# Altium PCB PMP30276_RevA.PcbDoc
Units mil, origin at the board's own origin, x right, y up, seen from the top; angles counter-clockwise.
Board outline 4075 x 1575 mil, 2 copper layers (Top Layer, Bottom Layer), stack 62 mil thick; 57 components, 35 nets, 126 pads, 6 vias.
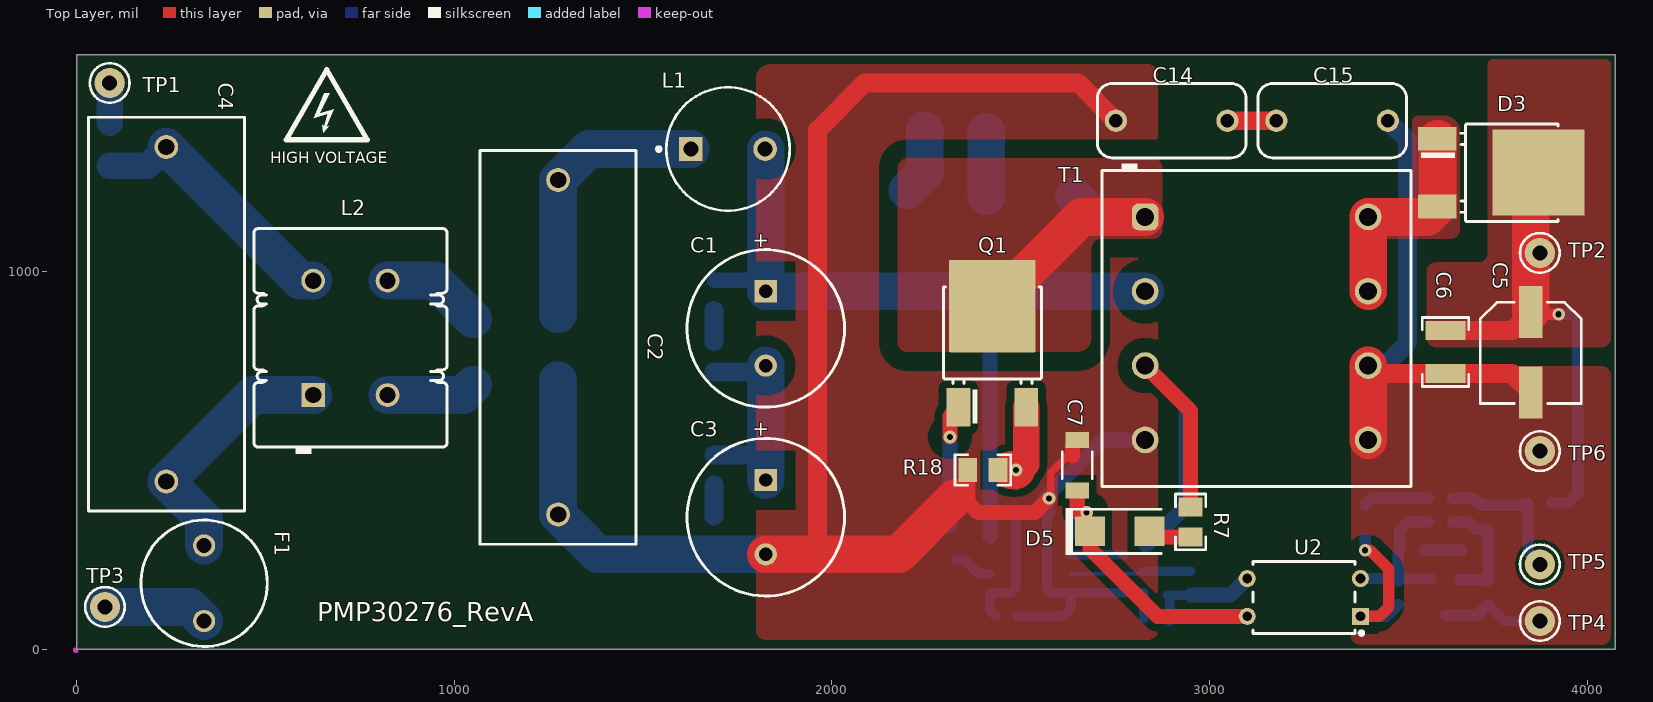
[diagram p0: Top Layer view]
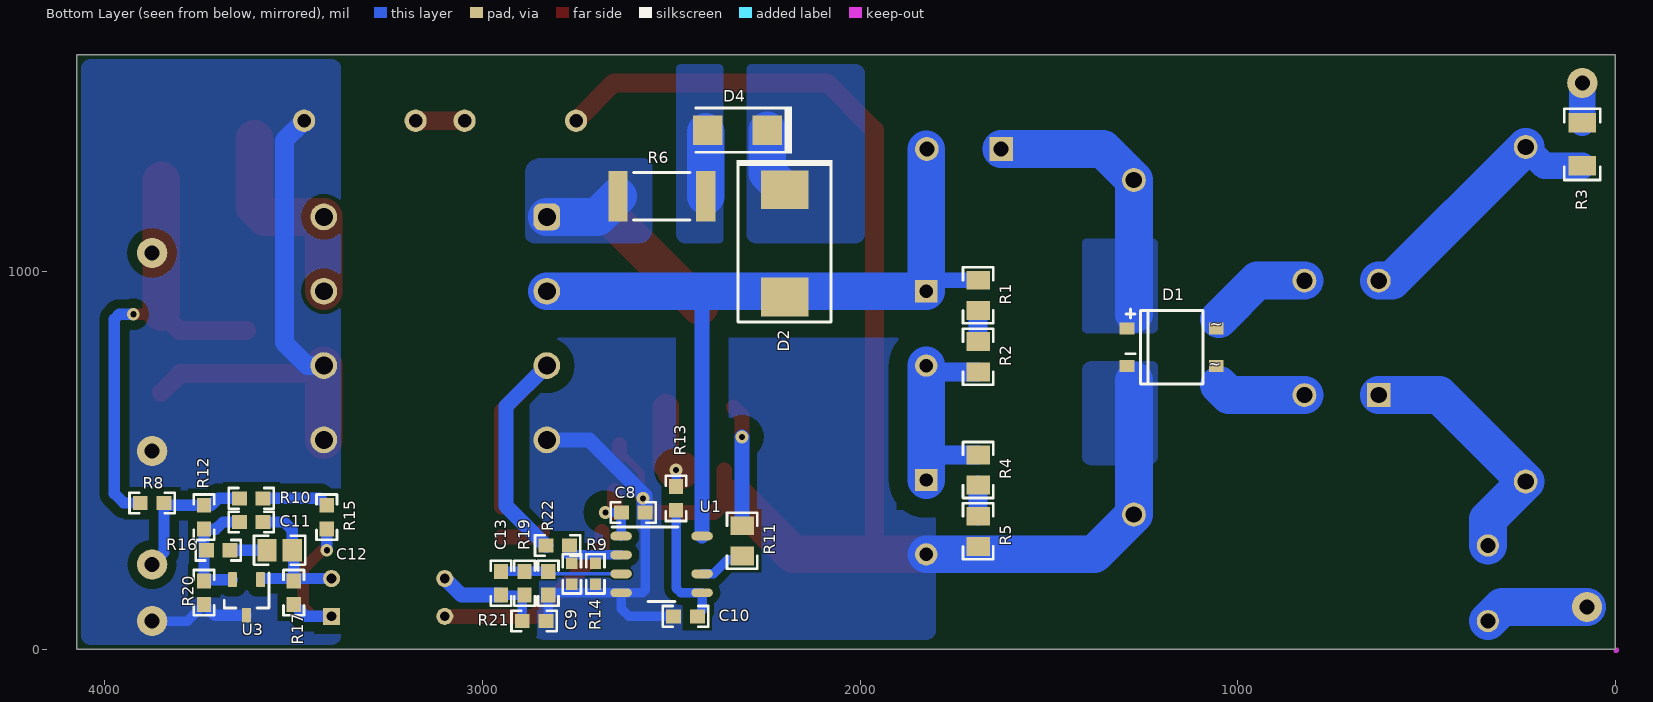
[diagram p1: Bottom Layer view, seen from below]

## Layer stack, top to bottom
Top Solder: solder mask 0.4, Solder Resist, Dk 3.5
Top Layer: signal copper 1.4
Dielectric1: core 59.2, FR-4, Dk 4.8
Bottom Layer: signal copper 1.4
Bottom Solder: solder mask 0.4, Solder Resist, Dk 3.5

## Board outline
0,0 4075,0 4075,1575 0,1575

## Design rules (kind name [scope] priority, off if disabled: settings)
AcuteAngle [All] p1: minimum=4.50000000000000E+0001 checktracksonly=FALSE
AssemblyTestPointUsage [All] p1: valid=2
Clearance Clearance_PGND_NetC1_2 [InNet('PGND') vs InNet('NetC1_2')] p1: gap=50 ignorepadtopadclearanceinfootprint=FALSE
Clearance "Clearance_PGND NETC1_1" [InNet('PGND') vs InNet('NetC1_1')] p2: gap=50 ignorepadtopadclearanceinfootprint=FALSE
Clearance "Clearance_PGND NETC9_1" [InNet('PGND') vs InNet('NetC13_2')] p3: gap=5 ignorepadtopadclearanceinfootprint=FALSE
Clearance Clearance_PGND [InNet('PGND')] p4: gap=20 ignorepadtopadclearanceinfootprint=FALSE except(50: Fill-Fill Fill-Poly Fill-Region Fill-Text Fill-Hole Poly-Poly Poly-Region Poly-Text Poly-Hole Region-Region Region-Text Region-Hole)
Clearance Clearance_Keepouts [((IsTrack Or IsArc) And Not InPoly) And IsFree and IsKeepOut vs ((IsTrack Or IsArc) And Not InPoly) And IsFree and IsKeepOut] p5: gap=0 ignorepadtopadclearanceinfootprint=FALSE
Clearance Clearance_BoardEdge_MountingHoles [OnCopper and InComponentClass('Mounting Holes') vs IsKeepOut] p6: gap=40 ignorepadtopadclearanceinfootprint=FALSE except(0: Arc-Hole Track-Hole SMDPad-Hole THPad-Hole Via-Hole Fill-Hole Poly-Hole Region-Hole Text-Hole)
Clearance Clearance_BoardEdge_Poly [OnCopper and InPoly vs IsKeepOut] p7: gap=25 ignorepadtopadclearanceinfootprint=FALSE except(0: Arc-Hole Track-Hole SMDPad-Hole THPad-Hole Via-Hole Fill-Hole Poly-Hole Region-Hole Text-Hole)
Clearance Clearance_BoardEdge [OnCopper and Not InComponentClass('Logo') and not InComponentClass('FiducialMark') and not InRegion(1000,500,4000,800) and Not IsKeepout vs IsKeepOut] p8: gap=75 ignorepadtopadclearanceinfootprint=FALSE except(0: Arc-Hole Track-Hole SMDPad-Hole THPad-Hole Via-Hole Fill-Hole Poly-Hole Region-Hole Text-Hole)
Clearance Clearance_Poly [InPolygon] p9: gap=25 ignorepadtopadclearanceinfootprint=FALSE except(0: Arc-Hole Track-Hole SMDPad-Hole THPad-Hole Via-Hole Fill-Hole Poly-Hole Region-Hole Text-Hole)
Clearance [All] p10: gap=7.87 ignorepadtopadclearanceinfootprint=FALSE except(0: Arc-Hole Track-Hole SMDPad-Hole THPad-Hole Via-Hole Fill-Hole Poly-Hole Region-Hole Text-Hole)
ComponentClearance ComponentClearance_MountingHoles_FiducialMarks [InComponentClass('Mounting Holes') vs InComponentClass('FiducialMark')] p1: gap=50 collisioncheckmode=3 verticalgap=10 showdistances=FALSE
ComponentClearance ComponentClearance_Shunt [InComponentClass('Header') vs InComponentClass('Shunt')] p2: gap=0 collisioncheckmode=3 verticalgap=0 showdistances=FALSE
ComponentClearance ComponentClearance_Logo [InComponentClass('Logo')] p3: gap=50 collisioncheckmode=3 verticalgap=10 showdistances=FALSE
ComponentClearance ComponentClearance_ScrewToNut [(HasFootprint('NY PMS 440 0025 PH')) vs (HasFootprint('Keystone_1902C'))] p4: gap=5 collisioncheckmode=3 verticalgap=10 showdistances=FALSE
ComponentClearance ComponentClearance_MountingHoles [InComponentClass('Mounting Holes')] p5: gap=250 collisioncheckmode=3 verticalgap=100000 showdistances=FALSE
ComponentClearance ComponentClearance_SmallPassives [HasFootprint('0201*') or HasFootprint('0402*') or HasFootprint('0508') or HasFootprint('0603*') or HasFootprint('0612') or HasFootprint('0805*') or HasFootprint('0815*') or HasFootprint('0830*') or HasFootprint('1206*') or HasFootprint('1210*') or HasFootprint('1808*') or HasFootprint('1812*') or HasFootprint('1825*') or HasFootprint('2010*') or HasFootprint('2220*') or HasFootprint('2225*') or HasFootprint('2512*') or HasFootprint('2728*') or HasFootprint('3518*') vs HasFootprint('0201*') or HasFootprint('0402*') or HasFootprint('0508') or HasFootprint('0603*') or HasFootprint('0612') or HasFootprint('0805*') or HasFootprint('0815*') or HasFootprint('0830*') or HasFootprint('1206*') or HasFootprint('1210*') or HasFootprint('1808*') or HasFootprint('1812*') or HasFootprint('1825*') or HasFootprint('2010*') or HasFootprint('2220*') or HasFootprint('2225*') or HasFootprint('2512*') or HasFootprint('2728*') or HasFootprint('3518*')] p6: gap=20 collisioncheckmode=3 verticalgap=10 showdistances=FALSE
ComponentClearance ComponentClearance_THtoSMT [IsThruComponent vs IsSMTComponent] p7: gap=20 collisioncheckmode=3 verticalgap=30 showdistances=FALSE
ComponentClearance ComponentClearance_THtoTH [IsThruComponent vs IsThruComponent] p8: gap=20 collisioncheckmode=3 verticalgap=30 showdistances=FALSE
ComponentClearance [All] p9: gap=20 collisioncheckmode=3 verticalgap=10 showdistances=FALSE
DiffPairsRouting [All] p1: maxlimit=100 minlimit=10 mostfreqgap=10 toplayer_minwidth=15 toplayer_maxwidth=15 toplayer_prefwidth=15 bottomlayer_minwidth=15 bottomlayer_maxwidth=15 bottomlayer_prefwidth=15 maxuncoupledlength=1000
FabricationTestPointUsage TestPointUsage [All] p1: valid=2 allowmultiple=FALSE
FabricationTestpoint Testpoint [All] p1: side=3 testpointundercomponent=TRUE minsize=40 maxsize=100 preferedsize=60 minholesize=0 maxholesize=40 preferedholesize=32 testpointgrid=1 allowsidetop=TRUE allowsidebottom=TRUE usegrid=TRUE gridtolerance=0.01
FanoutControl Fanout_LCC [IsLCC] p1: bgadir=Out bgaviamode=Centered fanoutstyle=Auto fanoutdirection=Alternating viagrid=1 // Fanout_LCC (Default Rule)
FanoutControl Fanout_BGA [IsBGA] p2: bgadir=Out bgaviamode=Centered fanoutstyle=Auto fanoutdirection=Alternating viagrid=1 // Fanout_BGA (Default Rule)
FanoutControl Fanout_Default [All] p4: bgadir=Out bgaviamode=Centered fanoutstyle=Auto fanoutdirection=Alternating viagrid=1 // Fanout_Default (Default Rule)
FanoutControl Fanout_Small [(CompPinCount < 5)] p5: bgadir=Out bgaviamode=Centered fanoutstyle=Auto fanoutdirection=OutThenIn viagrid=1 // Fanout_Small (Default Rule)
HoleSize [All] p1: absolutevalues=TRUE maxlimit=251 minlimit=8 maxpercent=80.000 minpercent=20.000
MinimumAnnularRing MinimumAnnularRing_ThermalPadVias [IsVia and InAnyComponent] p1: minimumring=5.91
MinimumAnnularRing [All] p2: minimumring=9
MinimumSolderMaskSliver MinimumSolderMaskSliver_Logo [InComponentClass('Logo') vs InComponentClass('Logo')] p1: minsoldermaskwidth=0.7
MinimumSolderMaskSliver [All] p2: minsoldermaskwidth=3.94
PlaneConnect [All] p1: planeconnectstyle=Direct reliefexpansion=10 reliefentries=4 reliefconductorwidth=10 reliefairgap=10
PolygonConnect [All] p1: connectstyle=Direct reliefconductorwidth=10 reliefentries=4 polygonreliefangle="90 Angle" airgapwidth=10
RoutingVias ThermalPadVias [IsVia and InAnyComponent] p1: holewidth=7.87 width=19.68 viastyle="Through Hole" minholewidth=7.87 minwidth=19.68 maxholewidth=12.99 maxwidth=23.62
RoutingVias [All] p2: holewidth=16 width=34 viastyle="Through Hole" minholewidth=7.87 minwidth=26 maxholewidth=40 maxwidth=65
SilkToBoardRegionClearance [Not ((IsComment or IsDesignator) And (Hide <> 'False')) and not InRegion(1000,500,4000,800)] p1:
SilkToSilkClearance SilkToSilkClearance_Pb-FreeLogo [(HasFootprint('Pb-Free_Overlay_Medium') OR HasFootprint('Pb-Free_Overlay_Small')) vs (HasFootprint('Pb-Free_Overlay_Medium') OR HasFootprint('Pb-Free_Overlay_Small'))] p1: silktosilkclearance=0
SilkToSilkClearance [All] p2: silktosilkclearance=4
SilkToSolderMaskClearance SilkToComonentPadClearance [IsPad and InAnycomponent] p1: minsilkscreentomaskgap=5 clearancetoexposedcopper=TRUE
SilkToSolderMaskClearance "Silk to Solder Mask Opening" [All] p2: minsilkscreentomaskgap=4 clearancetoexposedcopper=FALSE
SolderMaskExpansion [All] p1: expansion=1.97
Width [All] p1: maxlimit=100 minlimit=6 preferedwidth=10 checkconnectedcopper=TRUE
15 further rules are at their usual default settings.

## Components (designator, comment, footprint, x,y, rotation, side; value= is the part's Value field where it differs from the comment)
C1 "EEU-EE2V150" CAPPR5-10x20 1825,850 r270 top value=15uF
C2 "R474N322050A1K" B32913_2650x1050x1850 1275,800 r270 top value=0.22uF
C3 "EEU-EE2V150" CAPPR5-10x20 1825,350 r270 top value=15uF
C4 "R474N322050A1K" B32913_2650x1050x1850 237.5,887.5 r270 top value=0.22uF
C5 "16SVPF180M" CAPSMT_62_F61 3850,787.5 r270 top value=180uF
C6 "Used in BOM report" 1210 3625,787.5 r270 top value=DNP
C7 "C3216X7R1H475K160AC" 1206_180 2650,487.5 r90 top value=4.7uF
C8 "06035C104KAT2A" 0603 2600.95,362.5 r180 bottom value=0.1uF
C9 "Used in BOM report" 0603_HV 2763.45,200 r270 bottom value=DNP
C10 "Used in BOM report" 0603 2462.5,87.5 r0 bottom value=DNP
C11 "C0603C103J5RACTU" 0603 3612.5,337.5 r180 bottom value=0.01uF
C12 "Used in BOM report" 0805 3537.5,262.5 r0 bottom value=DNP
C13 "C1608X7R1H473K080AA" 0603 2950.95,175 r90 bottom value=0.047uF
C14 "DE2E3KY472MB3BM02F" KY_1000x500x1300 2900,1400 r180 top value=4700pF
C15 "DE2E3KY472MB3BM02F" KY_1000x500x1300 3325,1400 r180 top value=4700pF
D1 "MB8S-TP" MBS-1 1175,800 r180 bottom value=800V
D2 "SMCJ180A-TP" SMC_265 2200,1075 r270 bottom value=180V
D3 "MBRD5150TR" DPAK 3737.5,1262.5 r0 top
D4 "US1K-13-F" SMA 2325,1375 r0 bottom value=800V
D5 "ES1D-13-F" SMA 2762.5,312.5 r0 top value=200V
F1 "37205000001" FUSE_372 337.5,175 r270 top
"HIGH VOLTAGE" "DANGER HIGH VOLTAGE" IEC_HighVoltage_Small 662.5,1437.5 r0 top
L1 "768772221" WE-TI_8095 1725,1325 r0 top value=220uH
L2 "744822110" WE-CMB_Type_S 725,825 r90 top value=DNP
Q1 "IPD80R4K5P7ATMA1" DPAK 2425,775 r90 top value=800V
R1 "CRCW08051M50JNEA" 0805_HV 1687.5,937.5 r90 bottom value=1.5Meg
R2 "CRCW08051M50JNEA" 0805_HV 1687.5,775 r90 bottom value=1.5Meg
R3 "CRCW12060000Z0EA" 1206 87.5,1337.5 r270 bottom value=0
R4 "CRCW08051M50JNEA" 0805_HV 1687.5,475 r90 bottom value=1.5Meg
R5 "CRCW08051M50JNEA" 0805_HV 1687.5,312.5 r90 bottom value=1.5Meg
R6 "CRCW25120000Z0EG" 2512 2525,1200 r180 bottom value=0
R7 "CRCW080533R0JNEA" 0805_HV 2950,337.5 r90 top value=33
R8 "CRCW060349R9FKEA" 0603 3875,387.5 r0 bottom value=49.9
R9 "CRCW0603127KFKEA" 0603 2800.95,275 r0 bottom value=127k
R10 "CRCW06030000Z0EA" 0603 3612.5,400 r0 bottom value=0
R11 "CRCW08050000Z0EA" 0805_HV 2312.5,287.5 r90 bottom value=0
R12 "CRCW0603100KFKEA" 0603 3737.5,350 r90 bottom value=100k
R13 "CRCW06031K69FKEA" 0603 2487.5,400 r90 bottom value=1.69k
R14 "CRCW060334K8FKEA" 0603_HV 2700.95,200 r90 bottom value=34.8k
R15 "CRCW06032K00FKEA" 0603 3412.5,350 r90 bottom value=2.00k
R16 "Used in BOM report" 0603 3700,262.5 r180 bottom value=DNP
R17 "Used in BOM report" 0603 3500,150 r270 bottom value=DNP
R18 "ERJ-6RQF1R5V" 0805_HV 2400,475 r0 top value=1.50
R19 "CRCW0603100KFKEA" 0603 2888.45,175 r270 bottom value=100k
R20 "CRCW060326K1FKEA" 0603 3737.5,150 r90 bottom value=26.1k
R21 "CRCW060310K0FKEA" 0603 2863.45,75 r0 bottom value=10.0k
R22 "CRCW060322K1FKEA" 0603 2825.95,175 r90 bottom value=22.1k
T1 "750370833" Wurth_750370833 3125,850 r0 top value=1.5mH
TP1 "5000" Keystone5000 87.5,1500 r0 top
TP2 "5000" Keystone5000 3875,1050 r90 top
TP3 "5000" Keystone5000 75,112.5 r0 top
TP4 "5001" Keystone5001 3875,75 r0 top
TP5 "5000" Keystone5000 3875,225 r90 top
TP6 "5001" Keystone5001 3875,525 r90 top
U1 "UCC28740DR" D0007A_N 2525.95,225 r180 bottom
U2 "FOD817A" DIP-4 3250,137.5 r180 top
U3 "ATL431AIDBZR" DBZ0003A_N 3625,137.5 r270 bottom

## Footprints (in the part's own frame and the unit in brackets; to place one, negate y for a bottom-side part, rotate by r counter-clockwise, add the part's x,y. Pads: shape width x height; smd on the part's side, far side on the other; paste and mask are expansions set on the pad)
0603 [mm] "0603 from SM-752 data"
  rect 1x0.95 smd: 1(-0.8,0) 2(0.8,0)
  silkscreen extent -1.52,-0.69 1.52,0.69, body extent -0.87,-0.47 0.87,0.47, height 1
0603_HV [mil] "Ernesto recommended land pattern.  26 mil between pads."
  rect 30x30 smd: 1(-28,0) 2(28,0)
  silkscreen extent -52,-24 52,24, body extent -34,-19 34,19, height 39
0805 [mm] "0805 from SM-752 data"
  rect 1.3x1.5 smd: 1(-0.85,0) 2(0.85,0)
  silkscreen extent -1.72,-0.97 1.72,0.97, body extent -1.1,-0.72 1.1,0.72, height 1.45
0805_HV [mil] "0805 with 30mil clearance between pads"
  rect 50x63 smd: 1(-40,0) 2(40,0)
  silkscreen extent -74,-40 74,40, body extent -43,-29 43,29, height 57
1206 [mm] "1206 from SM-752 data"
  rect 1.3x1.85 smd: 1(-1.45,0) 2(1.45,0)
  silkscreen extent -2.4,-1.21 2.4,1.21, body extent -1.7,-0.9 1.7,0.9, height 1.35
1206_180 [mm] "1206_180"
  rect 1.1x1.6 smd: 1(-1.7,0) 2(1.7,0)
  silkscreen extent -0.9,-1 0.9,1, body extent -1.75,-0.95 1.75,0.95, height 1.8
1210 [mm] "1210 from SM-752 data"
  rect 1.3x2.7 smd: 1(-1.45,0) 2(1.45,0)
  silkscreen extent -2.32,-1.57 2.32,1.57, body extent -1.7,-1.35 1.7,1.35, height 1.35
2512 [mm] "Chip Resistor, Body 6.3x3.2mm, IPC Medium Density"
  rect 1.3x3.4 smd: 1(-2.95,0) 2(2.95,0)
  silkscreen extent -1.9,-1.6 1.9,1.6, body extent -3.22,-1.67 3.22,1.67, height 0.71
B32913_2650x1050x1850 [mm] "TH, 2-Leads, Body 26.5x10.5mm, Pin Spacing 22.5mm"
  round 1.6 hole 1.1: 1(-11.25,0) 2(11.25,0)
  silkscreen extent -13.25,-5.25 13.25,5.25, body extent -13.25,-5.25 13.25,5.25, height 18.5
CAPPR5-10x20 [mm] "Capacitor, Electrolytic, Radial; Body 10 x 20 mm (Dia.xH typ); Pin Spacing 5 mm (typ)"
  rect 1.5x1.5 hole 0.9: 1(-2.5,0)
  round 1.5 hole 0.9: 2(2.5,0)
  silkscreen extent -5.3,-5.3 5.3,5.3, body extent -5.21,-5.24 5.24,5.24, height 22.01
CAPSMT_62_F61 [mm] "6.3 x 5.8mm:  Chemi-Con F61"
  rect 3.5x1.6 smd: 1(-2.675,0.025) 2(2.725,0.025)
  silkscreen extent -3.34,-3.38 3.46,3.42, body extent -3.37,-3.38 3.46,3.43, height 6.1
D0007A_N [mm] "SOIC, 7-Leads, Body 4.9x3.9mm, Pitch 1.27mm, IPC Medium Density"
  oval 1.45x0.6 smd: 1(-2.725,1.905) 2(-2.725,0.635) 3(-2.725,-0.635) 4(-2.725,-1.905) 5(2.725,-1.905) 6(2.725,-0.635) 8(2.725,1.905)
  silkscreen extent -3.32,-2.5 1.1,2.52, body extent -3.01,-2.45 3.01,2.45, height 1.75
DBZ0003A_N [mm] "SOT23, 3-Leads, Body 2.9x1.3mm, Pitch 0.95mm, Lead Span 2.4mm, IPC Medium Density"
  rrect17% 1x0.6 smd: 1(-1.2,0.95) 2(-1.2,-0.95) 3(1.2,0)
  silkscreen extent -1.65,-1.5 0.7,1.5, body extent -1.26,-1.46 1.26,1.46, height 0.98
DIP-4 [mm] "DIP, 4-Leads, Body 6.86x4.83mm, Pitch 2.54mm"
  rect 1.15x1.15 hole 0.65: 1(-3.81,1.27)
  round 1.15 hole 0.65: 2(-3.81,-1.27) 3(3.81,-1.27) 4(3.81,1.27)
  silkscreen extent -4,-2.41 3.43,2.52, body extent -4.02,-2.41 4.02,2.41, height 5.59
DPAK [mm] "D-PAK, 3-Pads, Body 6.22x6.73mm (max), TO-252AA using nominal STEP model"
  rrect6% 2.6x1.6 smd: 1(-3.4,2.28) 3(-3.4,-2.28)
  rrect2% 6.2x5.8 smd paste-2.9: 4(3.4,0)
  silkscreen extent -4.5,-3.3 4.7,3.28, body extent -3.86,-3.29 5.84,3.29, height 2.48
FUSE_372 [mm] "LITTELFUSE"
  round 1.5 hole 1: 1(-2.54,0) 2(2.54,0)
  silkscreen extent -4.25,-4.25 4.25,4.25, body extent -4.25,-4.25 4.25,4.25, height 8
IEC_HighVoltage_Small [mil]
  silkscreen extent -107,-88 107,97
Keystone5000 [mil] "For Keystone 500x miniature loop terminals"
  round 80 hole 40: 1(0,0)
  silkscreen extent -52,-52 52,52, body extent -49,-49 49,49, height 182
Keystone5001 [mil] "For Keystone 500x miniature loop terminals"
  round 80 hole 40: 1(0,0)
  silkscreen extent -52,-52 52,52, body extent -49,-49 49,49, height 182
KY_1000x500x1300 [mm] "MuRata"
  round 1.5 hole 0.9: 1(-3.75,0) 2(3.75,0)
  silkscreen extent -5,-2.5 5,2.5, body extent -5,-2.5 5,2.5, height 13
MBS-1 [mm] "SOP, 4-Leads, Body 4.95x4.2mm"
  rect 1x0.8 smd: 1(-3,1.27) 2(3,1.27) 3(3,-1.27) 4(-3,-1.27)
  silkscreen extent -3.08,-2.48 2.1,2.56, body extent -3.45,-2.47 3.45,2.48, height 2.9
SMA [mm] "Molded Diode, 2-Leads, Body 4.3x2.6mm, IPC Medium Density, based on OnSemi component dimensions and land pattern"
  rect 2x2 smd: 1(-2,0) 2(2,0)
  silkscreen extent -3.66,-1.57 2.79,1.57, body extent -2.6,-1.3 2.6,1.3, height 2.42
SMC_265 [mm] "SMD, 2-Leads, Body 7.15x6.25mm"
  rect 2.6x3.2 smd: 1(-3.6,0) 2(3.6,0)
  silkscreen extent -5.6,-3.22 5.3,3.23, body extent -4.08,-3.13 4.08,3.13, height 2.65
WE-CMB_Type_S [mm] "TH, 4-Leads, Body 14.7x13mm"
  rect 1.6x1.6 hole 1.1: 1(-3.85,2.5)
  round 1.6 hole 1.1: 2(-3.85,-2.5) 3(3.85,-2.5) 4(3.85,2.5)
  silkscreen extent -7.8,-6.5 7.35,6.5, body extent -7.77,-6.5 7.77,6.5, height 20
WE-TI_8095 [mm] "Wurth WE-TI 8095"
  rect 1.6x1.6 hole 1: 1(-2.5,0)
  round 1.6 hole 1: 2(2.5,0)
  silkscreen extent -4.79,-4.15 4.15,4.15, body extent -4.12,-4.14 4.15,4.14, height 10
Wurth_750370833 [mm] "TH, 8-Leads, Body 21.24x20.78mm"
  rrect50% 1.8x1.8 hole 1.2: 1(-7.5,7.5)
  round 1.8 hole 1.2: 2(-7.5,2.5) 3(-7.5,-2.5) 4(-7.5,-7.5) 5(7.5,-7.5) 6(7.5,-2.5) 7(7.5,2.5) 8(7.5,7.5)
  silkscreen extent -10.39,-10.62 10.39,11.1, body extent -10.39,-10.62 10.39,10.62, height 15.88

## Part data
C1 C3: library part Capacitor_Polarized, "CAP, [Technology], 15uF, 350V, +/-xx%, xxOhm ESR, [MountType]", Alternate Manufacturer=-, Case/Package=Radial, Dielectric Material=Aluminium, Leakage Current=325uA, Manufacturer="Used in BOM report", Max Operating Temperature=105°C, Min Operating Temperature=-25°C, Package Quantity=200, Ripple Current=480mA, Supplier Part Number 1=P13651-ND, Tolerance_%=20%, Voltage=350V
C2 C4: library part B32913B5224K000, "CAP, Film, 0.22 µF, 440VAC,+/- 10%, TH", Cap_Case=26.5x10.5x18.5mm, Case/Package=Radial, Dielectric=PP, Manufacturer=TDK, Max Operating Temperature=110°C, Min Operating Temperature=-40°C, Tolerance_%=10, Value2=440VAC, ValueDisplayed=0.22µF, Voltage Rating (AC)=440V, Voltage Rating (DC)=1kV
C5: "CAP, Aluminum Polymer, 180 µF, 16 V,+/- 20%, 0.022 ohm, F61 SMD", Manufacturer=Panasonic, Tolerance_%=20, Value1="0.022 ohm", Value2=16V, ValueDisplayed=180µF
C6 C9 C10 C12: library part Capacitor, "CAP, CERM, xxxF, xxV, [TempCo], xx%, [PackageReference]", Alternate Manufacturer=-
C7: "CAP, CERM, 4.7 µF, 50 V,+/- 10%, X7R, 1206", Cap_Case=1206, Manufacturer=TDK, Supplier Part Number 1=445-8032-1-ND, TempCo=X7R, Tolerance_%=10, Value1="0.003158 ohm", Value2=50V, ValueDisplayed=4.7µF
C8: "CAP, CERM, 0.1 µF, 50 V, +/- 10%, X7R, 0603", Cap_Case=0603, Manufacturer=AVX, Supplier Part Number 1=478-5052-1-ND, TempCo=X7R, Tolerance_%=10, Value1=Unknown, Value2=50V, ValueDisplayed=0.1µF
C11: "CAP, CERM, 0.01 µF, 50 V, +/- 5%, X7R, 0603", Cap_Case=0603, Manufacturer=Kemet, Supplier Part Number 1=399-1092-1-ND, TempCo=X7R, Tolerance_%=5, Value1=Unknown, Value2=50V, ValueDisplayed=0.01µF
C13: "CAP, CERM, 0.047 µF, 50 V,+/- 10%, X7R, 0603", Cap_Case=0603, Manufacturer=TDK, Supplier Part Number 1=445-1313-1-ND, TempCo=X7R, Tolerance_%=10, Value1="0.049007 ohm", Value2=50V, ValueDisplayed=0.047µF
C14 C15: "CAP, CERM, 4700 pF, X1 250 VAC/Y2 300 VAC, +/- 20%, E, 10x5x13mm", Cap_Case=10x5x13mm, Manufacturer=MuRata, Supplier Part Number 1=490-9484-ND, TempCo=E, Tolerance_%=20, ValueDisplayed=4700pF
D1: "Diode, Switching-Bridge, 800 V, 0.5 A, TO269AA", Manufacturer="Micro Commercial Components", Supplier Part Number 1=MB8S-TPMSDKR-ND, Value1=0.5A, Value2=1V
D2: library part SMCJ160A-TP, "Diode, TVS, Uni, 180 V,", Manufacturer="Micro Commercial Components", Supplier Part Number 1=SMCJ180A-TPMSCT-ND, Value1=W
D3: library part DIODE_SCHOTTKY_A13C4, "Diode, Schottky, 150V, 5A, [PackageReference]", Alternate Manufacturer=-, Manufacturer="SMC Diode Solutions"
D4: "Diode, Fast Rectifier, 800 V, 1 A, SMA", Manufacturer="Diodes Inc.", Supplier Part Number 1=US1K-FDICT-ND, Value1=1A, Value2=1.7V
D5: "Diode, Ultrafast, 200 V, 1 A, SMA", Manufacturer="Diodes Inc.", Supplier Part Number 1=ES1D-FDICT-ND, Value1=1A, Value2=0.92V
F1: "Fuse, 0.5 A, 250VAC/VDC, TH", Irating_A=0.5, Manufacturer=Littelfuse, Supplier Part Number 1=WK4241CT-ND
"HIGH VOLTAGE": library part IEC_HighVoltage, "IEC 61010-1 High Voltage Warning"
L1: library part 768772681, "Inductor, Unshielded Drum Core, Powdered Iron, 220 µH,", Case/Package=Radial, Current Rating=900mA, Manufacturer="Wurth Elektronik", Max Operating Temperature=125°C, Min Operating Temperature=-40°C, Package Quantity=140, Saturation Current=1.3A, Self Resonant Frequency=3.7MHz, Supplier Part Number 1=732-4217-ND, Test Frequency=100KHz, Tolerance_%=10%, Value1="1.68 ohm", Value2=0.76A, ValueDisplayed=220µH
L2: "Coupled inductor, 10 mH, 1 A, 0.36 ohm, TH", Manufacturer="Wurth Elektronik", Supplier Part Number 1=732-1442-ND, ValueDisplayed=10mH
Q1: library part IPD80R1K0CEBTMA1, "MOSFET, N-CH, 800 V, DPAK", Alternate Manufacturer=None, Case/Package=TO-252-3, Continuous Drain Current (ID)=1.5A, Manufacturer="Infineon Technologies", Max Operating Temperature=150°C, Max Power Dissipation=13W, Min Operating Temperature=-55°C, Value1="? ohm"
R1 R2 R4 R5: "RES, 1.5 M, 5%, 0.125 W, 0805", Manufacturer=Vishay-Dale, Power_W=0.125, Supplier Part Number 1=541-1.5MACT-ND, TempCo="200 ppm/C", Tolerance_%=5, Value1=5%, Value2=0.125W, Value_Code=1M50, ValueDisplayed=1.5M
R3: "RES, 0, 5%, 0.25 W, 1206", Manufacturer=Vishay-Dale, Power_W=0.25, Supplier Part Number 1=541-0.0ECT-ND, TempCo="200 ppm/C", Tolerance_%=5, Value1=5%, Value2=0.25W, Value_Code=0000, ValueDisplayed=0
R6: "RES, 0, 5%, 1 W, AEC-Q200 Grade 0, 2512", Manufacturer=Vishay-Dale, Power_W=1, Supplier Part Number 1=541-0.0XCT-ND, TempCo=ppm/C, Tolerance_%=5, Value1=5%, Value2=1W, Value_Code=0000, ValueDisplayed=0
R7: "RES, 33, 5%, 0.125 W, 0805", Manufacturer=Vishay-Dale, Power_W=0.125, Supplier Part Number 1=541-33ACT-ND, TempCo="200 ppm/C", Tolerance_%=5, Value1=5%, Value2=0.125W, Value_Code=33R0, ValueDisplayed=33
R8: "RES, 49.9, 1%, 0.1 W, 0603", Manufacturer=Vishay-Dale, Power_W=0.1, Supplier Part Number 1=541-49.9HCT-ND, TempCo="100 ppm/C", Tolerance_%=1, Value1=1%, Value2=0.1W, Value_Code=49R9, ValueDisplayed=49.9
R9: "RES, 127 k, 1%, 0.1 W, 0603", Manufacturer=Vishay-Dale, Power_W=0.1, Supplier Part Number 1=541-127KHCT-ND, TempCo="100 ppm/C", Tolerance_%=1, Value1=1%, Value2=0.1W, Value_Code=127k
R10: "RES, 0, 5%, 0.1 W, 0603", Manufacturer=Vishay-Dale, Power_W=0.1, Supplier Part Number 1=541-0.0GCT-ND, TempCo="200 ppm/C", Tolerance_%=5, Value1=5%, Value2=0.1W, Value_Code=0000, ValueDisplayed=0
R11: "RES, 0, 5%, 0.125 W, 0805", Manufacturer=Vishay-Dale, Power_W=0.125, Supplier Part Number 1=541-0.0ACT-ND, TempCo="200 ppm/C", Tolerance_%=5, Value1=5%, Value2=0.125W, Value_Code=0000, ValueDisplayed=0
R12 R19: "RES, 100 k, 1%, 0.1 W, 0603", Manufacturer=Vishay-Dale, Power_W=0.1, Supplier Part Number 1=541-100KHCT-ND, TempCo="100 ppm/C", Tolerance_%=1, Value1=1%, Value2=0.1W, Value_Code=100k
R13: "RES, 1.69 k, 1%, 0.1 W, 0603", Manufacturer=Vishay-Dale, Power_W=0.1, Supplier Part Number 1=541-1.69KHCT-ND, TempCo="100 ppm/C", Tolerance_%=1, Value1=1%, Value2=0.1W, Value_Code=1k69, ValueDisplayed=1.69k
R14: "RES, 34.8 k, 1%, 0.1 W, 0603", Manufacturer=Vishay-Dale, Power_W=0.1, Supplier Part Number 1=541-34.8KHCT-ND, TempCo="100 ppm/C", Tolerance_%=1, Value1=1%, Value2=0.1W, Value_Code=34k8, ValueDisplayed=34.8k
R15: "RES, 2.00 k, 1%, 0.1 W, 0603", Manufacturer=Vishay-Dale, Power_W=0.1, Supplier Part Number 1=541-2.00KHCT-ND, TempCo="100 ppm/C", Tolerance_%=1, Value1=1%, Value2=0.1W, Value_Code=2k00, ValueDisplayed=2.00k
R16 R17: library part Resistor, "RES, xxx ohm, x%, xW, [PackageReference]", Alternate Manufacturer=-
R18: "RES, 1.50, 1%, 0.125 W, 0805", Manufacturer=Panasonic, Power_W=0.125, Supplier Part Number 1=P1.5DCT-ND, TempCo="200 ppm/C", Tolerance_%=1, Value1=1%, Value2=0.125W, Value_Code=1R50, ValueDisplayed=1.50
R20: "RES, 26.1 k, 1%, 0.1 W, 0603", Manufacturer=Vishay-Dale, Power_W=0.1, Supplier Part Number 1=541-26.1KHCT-ND, TempCo="100 ppm/C", Tolerance_%=1, Value1=1%, Value2=0.1W, Value_Code=26k1, ValueDisplayed=26.1k
R21: "RES, 10.0 k, 1%, 0.1 W, 0603", Manufacturer=Vishay-Dale, Power_W=0.1, Supplier Part Number 1=541-10.0KHCT-ND, TempCo="100 ppm/C", Tolerance_%=1, Value1=1%, Value2=0.1W, Value_Code=10k0, ValueDisplayed=10.0k
R22: "RES, 22.1 k, 1%, 0.1 W, 0603", Manufacturer=Vishay-Dale, Power_W=0.1, Supplier Part Number 1=541-22.1KHCT-ND, TempCo="100 ppm/C", Tolerance_%=1, Value1=1%, Value2=0.1W, Value_Code=22k1, ValueDisplayed=22.1k
T1: library part CMP-0077094-1, "Transformer, 1500 uH, TH", Manufacturer="Wurth Elektronik", ValueDisplayed=1.5mH
TP1 TP2 TP3 TP5: "Test Point, Miniature, Red, TH", Color=Red, Manufacturer=Keystone, Supplier Part Number 1=36-5000-ND
TP4 TP6: "Test Point, Miniature, Black, TH", Color=Black, Manufacturer=Keystone, Supplier Part Number 1=36-5001-ND
U1: "Constant-Voltage, Constant-Current Flyback Controller Using Opto-Coupler Feedback, D0007A", Alternate Manufacturer="Texas Instruments", Alternate PartNumber=UCC28740D
U2: "Optocoupler, 5 kV, 80-160% CTR, TH", Manufacturer="Fairchild Semiconductor", Supplier Part Number 1=FOD817A-ND, Voltage_Isolation_Vrms=5000V
U3: "2.5V Low Iq Adjustable Precision Shunt Regulator, DBZ0003A (SOT-23-3)", Alternate Manufacturer="Texas Instruments"

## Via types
v1: diameter 34, hole 16, Top Layer to Bottom Layer, 6 vias

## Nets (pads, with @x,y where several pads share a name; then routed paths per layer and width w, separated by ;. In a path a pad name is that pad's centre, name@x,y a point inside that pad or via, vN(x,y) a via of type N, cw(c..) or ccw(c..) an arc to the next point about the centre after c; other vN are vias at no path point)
12Vout: C5.1 C6.1 D3.4 R8.2 TP2.1 | length 1257
  Top Layer w30: C5.1@3869.72,911.58 3893.8,887.5 v1(3925,887.5)
  Top Layer w50: C6.1 3802.73,844.59 C5.1
  Top Layer w100: C5.1 D3.4@3850.97,1242.11
  Bottom Layer w30: R8.2 3950,387.5 3975,412.5 3975,875 3962.5,887.5 v1(3925,887.5)
GND: C5.2 C6.2 C15.1 R20.1 T1.5 T1.6 TP4.1 TP6.1 U3.3 | length 1676
  Top Layer w50: T1.6 3441.44,730.41 C6.2 3800.79,730.41 C5.2
  Top Layer w100: T1.5 T1.6
  Bottom Layer w25: R20.1 3781,75 TP4.1
  Bottom Layer w30: U3.3 3709.25,90.26 R20.1
  Bottom Layer w50: T1.6 3464.07,751.57 3525,812.5 3525,1347.64 C15.1
NetC1_1: C1.1 D2.2 L1.2 R1.2 T1.2 U1.8 | length 2139.1
  Bottom Layer w40: R1.2 C1.1@1795.93,977.5 ; 2412.5,948.43 2418.67,942.26 U1.8
  Bottom Layer w100: L1.2@1825,1323.43 C1.1 2412.5,948.43 T1.2
NetC1_2: C1.2 C3.1 R2.1 R4.2 | length 551.6
  Bottom Layer w50: R4.2 1815,515 ; R2.1 C1.2@1808.43,735
  Bottom Layer w100: C3.1 C1.2
NetC2_1: C2.1 D1.1 L1.1 | length 741
  Bottom Layer w100: 1275,887.5 C2.1 1357.09,1325 L1.1
NetC4_1: C4.1 L2.4 R3.2 | length 706.4
  Bottom Layer w70: R3.2 187.5,1280.41 C4.1
  Bottom Layer w100: C4.1 591.34,976.57 L2.4
NetC4_2: C4.2 F1.1 L2.1 | length 694.9
  Bottom Layer w100: F1.1 337.5,344.59 C4.2 466.34,673.43 L2.1
NetC7_1: C7.1 C8.1 D5.1 U1.1 U2.4 | length 700
  Top Layer w40: 2650,362.5 C7.1 ; D5.1 2683.76,266.24 2862.5,87.5 U2.4
  Bottom Layer w25: U1.1 2633.24,361.71 C8.1 v1(2675,362.5)
NetC9_1: C9.1 R9.1 R14.2 U1.2 | length 141.8
  Bottom Layer w25: U1.2 2775,250
NetC10_1: C10.1 R13.1 U1.5 | length 349.1
  Bottom Layer w25: C10.1@2434.5,87.5 2418.67,103.33 U1.5 2475,150 2487.5,162.5 R13.1
NetC11_1: C11.1 R12.1 R16.1 R20.2 U3.2 | length 310.2
  Bottom Layer w30: C11.1 3687.5,337.5 3706.5,318.5 R12.1 R20.2 ; U3.2 R20.2@3734.25,184.74
NetC11_2: C11.2 C12.1 R17.1 U2.2 U3.1 | length 405.4
  Bottom Layer w25: U3.1@3584.84,187.5 U3.1
  Bottom Layer w30: U2.2 R17.1@3500,187.5 ; R17.1 R17.1@3500,187.5 ; C12.1@3500,258.46 R17.1@3500,187.5 ; C12.1 3504.04,316.54 3525,337.5 C11.2 ; U3.1@3584.84,187.5 R17.1@3500,187.5
NetC12_2: C12.2 R16.2 | length 97.5
  Bottom Layer w30: C12.2 R16.2
NetC13_1: C13.1 R19.2 R21.2 U2.3 | length 291.8
  Bottom Layer w25: R19.2 C13.1 ; R21.2 R19.2@2894.95,137.01
  Bottom Layer w40: C13.1 3056,143.5 U2.3
NetC13_2: C13.2 R19.1 R22.2 U1.3 | length 317.7
  Bottom Layer w10: U1.3 R22.2@2825.95,200
  Bottom Layer w25: R22.2 R19.1 C13.2
NetC14_1: C14.1 C15.2 | length 129.7
  Top Layer w50: C14.1 C15.2
NetD1_2: D1.2 L2.3 | length 268.6
  Bottom Layer w100: L2.3 948.43,976.57 1050,875
NetD1_3: D1.3 L2.2 | length 237.6
  Bottom Layer w100: L2.2 1023.43,673.43 1050,700
NetD2_1: D2.1 D4.1 | length 177.4
  Bottom Layer w100: D2.1 2246.26,1262.99 D4.1
NetD3_1: D3.1 D3.3 T1.7 T1.8 | length 571.1
  Top Layer w100: T1.7 T1.8 3576.18,1145.28 D3.3 D3.1
NetD4_2: D4.2 R6.2 | length 169.9
  Bottom Layer w100: R6.2 D4.2@2408.86,1369.88
NetD5_2: D5.2 R7.1 | length 115
  Top Layer w40: D5.2 2856.24,297.5 R7.1
NetF1_2: F1.2 TP3.1 | length 278
  Bottom Layer w100: TP3.1 300,112.5 F1.2
NetQ1_1: Q1.1 R11.2 | length 323.1
  Top Layer w40: v1(2312.5,562.5) 2312.5,618.41 Q1.1
  Bottom Layer w40: R11.2 v1(2312.5,562.5)
NetQ1_3: Q1.3 R13.2 R18.2 | length 207.4
  Top Layer w70: 2514.76,489.76 Q1.3
  Top Layer w100: v1@2475,475 v1(2487.5,475)
  Bottom Layer w25: R13.2 v1(2487.5,475)
NetQ1_4: Q1.4 R6.1 T1.1 | length 713.9
  Top Layer w100: Q1.4 2661.42,1145.28 T1.1
  Bottom Layer w100: R6.1 2695.87,1145.28 T1.1
NetR1_1: R1.1 R2.2 | length 82.5
  Bottom Layer w50: R2.2 R1.1
NetR3_1: R3.1 TP1.1 | length 105.4
  Bottom Layer w70: R3.1 TP1.1
NetR4_1: R4.1 R5.2 | length 82.5
  Bottom Layer w50: R5.2 R4.1
NetR7_2: R7.2 R9.2 T1.3 | length 988.6
  Top Layer w40: T1.3 2950,631.3 R7.2
  Bottom Layer w40: T1.3 2937.5,643.8 2937.5,380.05 R9.2
NetR8_1: R8.1 R10.2 R12.2 TP5.1 | length 385.2
  Bottom Layer w30: R10.2 3700,400 3718.5,381.5 R12.2 3837.5,381.5 R8.1 3843.5,256.5 TP5.1
NetR10_1: R10.1 R15.2 | length 176.2
  Bottom Layer w30: R15.2 3431,400 R10.1
NetR11_1: R11.1 U1.6 | length 105.7
  Bottom Layer w25: R11.1@2328.45,237.5 2350.95,237.5 2388.45,200 U1.6
NetR15_1: R15.1 R17.2 U2.1 | length 412.4
  Top Layer w30: U2.1 3450,87.5 3475,112.5 3475,212.5 3425,262.5 v1(3412.5,262.5)
  Bottom Layer w30: U2.1 3469,87.5 R17.2 ; v1(3412.5,262.5) 3412.5,293.5
PGND: C2.2 C3.2 C7.2 C8.2 C9.2 C10.2 C14.2 D1.4 R5.1 R14.1 R18.1 R21.1 R22.1 T1.4 U1.4 | length 5098.9
  Top Layer w20: v1(2575,400) 2579.76,404.76 2579.76,467.26 2625,512.5 2637.5,512.5
  Top Layer w40: R18.1 2360,390 2387.5,362.5 2537.5,362.5 v1(2575,400) ; 2637.5,512.5 C7.2@2637.5,541.93
  Top Layer w50: 1962.5,251.57 1962.5,1375 2087.5,1500 2652.36,1500 C14.2
  Top Layer w100: C3.2 1962.5,251.57 2176.57,251.57 2325,400
  Bottom Layer w25: C10.2@2490.5,87.5 2612.5,87.5 2633.24,108.24 U1.4 ; C8.2 2569.46,156.5 2575.95,150 U1.4 ; R21.1@2825.95,81 R22.1 ; R22.1@2825.95,150 U1.4
  Bottom Layer w40: C8.2 v1@2569.46,400 ; v1@2569.46,406.96 2717.22,554.72 T1.4
  Bottom Layer w100: 1275,712.5 C2.2 1380.51,251.57 C3.2

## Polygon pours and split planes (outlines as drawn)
NetQ1_4 on Top Layer "Top Layer-No Net" (solid, remove dead copper, pour order 2): 2200,787.5 cw(c2200,812.5) 2175,812.5 2175,1275 cw(c2200,1275) 2200,1300 2850,1300 cw(c2850,1275) 2875,1275 2875,1112.5 cw(c2850,1112.5) 2850,1087.5 2712.5,1087.5 ccw(c2712.5,1062.5) 2687.5,1062.5 2687.5,825 cw(c2650,825) 2650,787.5
PGND on Top Layer "Top Layer-No Net 1" (solid, pour order 18): 2862.5,50 cw(c2837.5,50) 2837.5,25 1825,25 cw(c1825,50) 1800,50 1800,1512.5 cw(c1837.5,1512.5) 1837.5,1550 2837.5,1550 cw(c2837.5,1525) 2862.5,1525
12Vout on Top Layer "Top Layer-No Net 2" (solid, pour order 20): 4037.5,800 ccw(c4037.5,825) 4062.5,825 4062.5,1550 ccw(c4050,1550) 4050,1562.5 3750,1562.5 ccw(c3750,1550) 3737.5,1550 3737.5,1050 cw(c3712.5,1050) 3712.5,1025 3600,1025 ccw(c3600,1000) 3575,1000 3575,825 ccw(c3600,825) 3600,800
NetD3_1 on Top Layer "Top Layer-No Net 3" (solid, remove dead copper, pour order 22): 3447.5,1087.5 3637.5,1087.5 ccw(c3637.5,1112.5) 3662.5,1112.5 3662.5,1375 ccw(c3625,1375) 3625,1412.5 3550,1412.5 ccw(c3550,1400) 3537.5,1400 3537.5,1212.5 cw(c3512.5,1212.5) 3491.86,1198.4
GND on Top Layer "Top Layer-No Net 4" (solid, remove dead copper, pour order 24): 3375,750 4037.5,750 cw(c4037.5,725) 4062.5,725 4062.5,37.5 cw(c4037.5,37.5) 4037.5,12.5 3400,12.5 cw(c3400,37.5) 3375,37.5
PGND on Bottom Layer "Bottom Layer-No Net" (solid, remove dead copper, pour order 10): 1825,25 cw(c1825,50) 1800,50 1800,800 cw(c1825,800) 1825,825 2837.5,825 cw(c2837.5,787.5) 2875,787.5 2875,62.5 cw(c2837.5,62.5) 2837.5,25
NetD2_1 on Bottom Layer "Bottom Layer-No Net 1" (solid, pour order 12): 2012.5,1075 cw(c2012.5,1100) 1987.5,1100 1987.5,1525 cw(c2012.5,1525) 2012.5,1550 2287.5,1550 cw(c2287.5,1537.5) 2300,1537.5 2300,1100 cw(c2275,1100) 2275,1075
NetD4_2 on Bottom Layer "Bottom Layer-No Net 2" (solid, pour order 14): 2375,1075 cw(c2375,1087.5) 2362.5,1087.5 2362.5,1537.5 cw(c2375,1537.5) 2375,1550 2475,1550 cw(c2475,1537.5) 2487.5,1537.5 2487.5,1100 cw(c2462.5,1100) 2462.5,1075
NetQ1_4 on Bottom Layer "Bottom Layer-No Net 3" (solid, pour order 16): 2575,1300 ccw(c2575,1275) 2550,1275 2550,1112.5 ccw(c2587.5,1112.5) 2587.5,1075 2862.5,1075 ccw(c2862.5,1100) 2887.5,1100 2887.5,1262.5 ccw(c2850,1262.5) 2850,1300
GND on Bottom Layer "Bottom Layer-No Net 4" (solid, remove dead copper, pour order 26): 3375,1537.5 cw(c3400,1537.5) 3400,1562.5 4037.5,1562.5 cw(c4037.5,1537.5) 4062.5,1537.5 4062.5,37.5 cw(c4037.5,37.5) 4037.5,12.5 3400,12.5 cw(c3400,37.5) 3375,37.5
PGND on Bottom Layer "Bottom Layer-No Net 5" (solid, remove dead copper, pour order 28): 1212.5,750 cw(c1225,750) 1225,762.5 1387.5,762.5 cw(c1387.5,737.5) 1412.5,737.5 1412.5,512.5 cw(c1387.5,512.5) 1387.5,487.5 1237.5,487.5 cw(c1237.5,512.5) 1212.5,512.5
NetC2_1 on Bottom Layer "Bottom Layer-No Net 6" (solid, remove dead copper, pour order 30): 1212.5,850 ccw(c1225,850) 1225,837.5 1400,837.5 ccw(c1400,850) 1412.5,850 1412.5,1075 ccw(c1400,1075) 1400,1087.5 1225,1087.5 ccw(c1225,1075) 1212.5,1075

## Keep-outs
Keep-Out Layer:
  lines w10: -5,0 ccw(c0,0) 0,-5 cw(c0,0) -5,0 ; -5,3450 cw(c0,3450) 0,3455 ccw(c0,3450) -5,3450 ; 4950,-5 ccw(c4950,0) 4955,0 cw(c4950,0) 4950,-5 ; 4950,3455 cw(c4950,3450) 4955,3450 ccw(c4950,3450) 4950,3455
  text ".Layer_Name" at 577,-858.49 h60

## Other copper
Top Layer:
  text ".Layer_Name" at 577,-858.49 h60
Bottom Layer:
  text ".Layer_Name" at 577,-858.49 h60

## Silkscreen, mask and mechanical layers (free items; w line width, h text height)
Top Overlay:
  text "PMP30276_RevA" at 637.5,75 h50
  text ".Layer_Name" at 577,-858.49 h40
Bottom Overlay:
  text ".Layer_Name" at 577,-858.49 h30
Top Paste:
  text ".Layer_Name" at 577,-858.49 h60
Bottom Paste:
  text ".Layer_Name" at 577,-858.49 h60
Top Solder:
  text ".Layer_Name" at 577,-858.49 h60
  text ".Layer_Name" at 577,-858.49 h60
Bottom Solder:
  text ".Layer_Name" at 577,-858.49 h60
Drill Guide:
  text ".Layer_Name" at 577,-858.49 h60
M1 Board Outline:
  the board outline again, w10
  text ".Layer_Name" at 577,-858.49 h60
M2 Board Dimensions:
  rectangle: 0,-275 125,-150
  rectangle: 125,-400 500,-275
  lines w7: 0,-275 1000,-275 ; 125,-400 125,-150 ; 250,-400 250,-150 ; 500,-400 500,-150 ; 750,-400 750,-150 ; 0,-400 1000,-400 1000,-150 0,-150 0,-400
  text ".Layer_Name" at 577,-858.49 h60
M3 3D STEP Top:
  text ".Layer_Name" at 577,-858.49 h60
M4 3D STEP Bottom:
  text ".Layer_Name" at 577,-858.49 h60
M5 Assembly Top:
  lines w10: -292,-930.17 6308,-930.17 ; -292,-726.83 6310,-726.83 ; -292,-523.5 -292,-1133.5 3713,-1133.5 6310,-1133.5 6310,-523.5 -291.5,-523.5 -291.5,-1133.5 1284,-1133.5 ; 2173,-1133.5 2173,-523.5 ; 3440,-726.83 3440,-523.5 ; 4280,-726.83 4280,-523.5 ; 4902,-1140 4902,-937.17
  text "PCB VIEWED FROM TOP SIDE" at -228.5,-655.67 h60
  text "BOARD #:" at 2248,-655.67 h60
  text ".PRJ_Number" at 2793.5,-655.67 h60
  text "REV:" at 3638,-655.67 h60
  text ".PCB_Rev" at 3929.5,-655.67 h60
  text "SVN REV:" at 4476,-655.67 h60
  text ".VersionControl_RevNumber" at 4982,-655.67 h60
  text "TID #:" at 2248,-859 h60
  text ".TID" at 2793.5,-859 h60
  text "PLOT NAME =" at -228.5,-1064.34 h60
  text ".plot_File_Name" at 577,-1064.34 h60
  text "GENERATED    :" at 2250,-1064.34 h60
  text ".Print_Date" at 3119.5,-1064.34 h60
  text ".Print_Time" at 3848.5,-1064.34 h60
  text "TEXAS INSTRUMENTS" at 5113,-1064.34 h60
M6 Assembly Bottom:
  lines w10: -292.5,-727.33 6309.5,-727.33 ; -290.5,-930.67 6309.5,-930.67 ; 1115.5,-1140.5 1115.5,-937.67 ; 1737.5,-727.33 1737.5,-524 ; 2577.5,-727.33 2577.5,-524 ; 3844.5,-1134 3844.5,-524 ; 4733.5,-1134 6309,-1134 6309,-524 -292.5,-524 -292.5,-1134 2304.5,-1134 6309.5,-1134 6309.5,-524
  text ".VersionControl_RevNumber" at 1035.5,-656.17 h60
  text "SVN REV:" at 1541.5,-656.17 h60
  text ".PCB_Rev" at 2088,-656.17 h60
  text "REV:" at 2379.5,-656.17 h60
  text ".PRJ_Number" at 3224,-656.17 h60
  text "BOARD #:" at 3769.5,-656.17 h60
  text "PCB VIEWED FROM BOTTOM SIDE" at 6246,-656.17 h60
  text ".TID" at 3224,-859.5 h60
  text "TID #:" at 3769.5,-859.5 h60
  text "TEXAS INSTRUMENTS" at 904.5,-1064.84 h60
  text ".Print_Time" at 2169,-1064.84 h60
  text ".Print_Date" at 2898,-1064.84 h60
  text "GENERATED    :" at 3767.5,-1064.84 h60
  text ".plot_File_Name" at 5440.5,-1064.84 h60
  text "PLOT NAME =" at 6246,-1064.84 h60
M9 Title Sheet:
  drawing of 57 lines, arcs and shapes, not listed
  text "1" at 739.84,8036.5 h70
  text "2" at 3235.5,8036.5 h70
  text "3" at 5724.84,8036.5 h70
  text "4" at 8231.51,8036.5 h70
  text "5" at 10730.5,8036.5 h70
  text "6" at 13235.5,8036.5 h70
  text "A" at -416.5,6893.5 h70
  text "A" at 14383.5,6893.5 h70
  text "B" at -416.5,4513.5 h70
  text "B" at 14383.5,4513.5 h70
  text "C" at -416.5,2138.5 h70
  text "C" at 14383.5,2138.5 h70
  text "PROJECT TITLE:" at 11343.5,277.5 h45
  text ".PRJ_Title" at 11393.5,144.17 h70
  text "DESIGNED FOR:" at 11343.5,-23.5 h45
  text ".PRJ_Customer" at 11393.5,-163.5 h70
  text "D" at -416.5,-231.5 h70
  text "D" at 14383.5,-231.5 h70
  text "FILE NAME:" at 11343.5,-323.5 h45
  text ".PCB_File_Name_No_Path" at 11393.5,-443.5 h70
  text "Texas Instruments (TI) and/or its licensors do not warrant the accuracy or completeness of this specification" at 6374,-605.34 h45
  text "ENGINEER:" at 11343.5,-613.5 h45
  text "LAYOUT BY:" at 12848.5,-613.5 h45
  text "or any information contained therein. TI and/or its licensors do not warrant that this design will meet" at 6329.01,-718 h45
  text ".PRJ_Engineer" at 11393.5,-768.49 h70
  text ".PCB_Layout" at 12899,-768.49 h70
  text "the specifications, will be suitable for your application or fit for any particular purpose, or will operate in" at 6329.01,-830.67 h45
  text ".Layer_Name" at 577,-858.49 h60
  text "ALTIUM DESIGNER VERSION:" at 12848.5,-923.5 h45
  text "an implementation. TI and/or its licensors do not warrant that the design is production worthy. You should" at 6329.01,-943.33 h45
  text "completely validate and test your design implementation to confirm the system functionality for your application." at 6374,-1056 h45
  text ".print_Scale" at 11393.5,-1056.83 h70
  text ".Application_BuildNumber" at 12899,-1056.83 h70
  text "1" at 739.84,-1263.5 h70
  text "2" at 3235.5,-1263.5 h70
  text "3" at 5724.84,-1263.5 h70
  text "4" at 8231.51,-1263.5 h70
  text "5" at 10730.5,-1263.5 h70
  text "6" at 13235.5,-1263.5 h70
M10 Fab Notes:
  text ".Layer_Name" at 577,-858.49 h60
M11 Gerber Information:
  lines w10: -292,-930.17 6308,-930.17 ; -292,-726.83 6310,-726.83 ; -292,-523.5 -292,-1133.5 3713,-1133.5 6310,-1133.5 6310,-523.5 -291.5,-523.5 -291.5,-1133.5 1284,-1133.5 ; 2173,-1133.5 2173,-523.5 ; 3440,-726.83 3440,-523.5 ; 4280,-726.83 4280,-523.5 ; 4902,-1140 4902,-937.17
  text "ALL ARTWORK VIEWED FROM TOP SIDE" at -228.5,-655.67 h60
  text "BOARD #:" at 2248,-655.67 h60
  text ".PRJ_Number" at 2793.5,-655.67 h60
  text "REV:" at 3638,-655.67 h60
  text ".PCB_Rev" at 3929.5,-655.67 h60
  text "SVN REV:" at 4476,-655.67 h60
  text ".VersionControl_RevNumber" at 4982,-655.67 h60
  text "LAYER NAME =" at -228.5,-858.49 h60
  text "TID #:" at 2248,-859 h60
  text ".TID" at 2793.5,-859 h60
  text "PLOT NAME =" at -228.5,-1064.34 h60
  text ".plot_File_Name" at 577,-1064.34 h60
  text "GENERATED    :" at 2250,-1064.34 h60
  text ".Print_Date" at 3119.5,-1064.34 h60
  text ".Print_Time" at 3848.5,-1064.34 h60
  text "TEXAS INSTRUMENTS" at 5113,-1064.34 h60
M12 Stackup:
  text ".Layer_Name" at 577,-858.49 h60
M13 Component Bodies Top:
  text ".Layer_Name" at 577,-858.49 h60
M14 Component Bodies Bottom:
  text ".Layer_Name" at 577,-858.49 h60
M15 Courtyards Top:
  text ".Layer_Name" at 577,-858.49 h60
M16 Courtyards Bottom:
  text ".Layer_Name" at 577,-858.49 h60
Drill Drawing:
  text ".Layer_Name" at 577,-858.49 h60

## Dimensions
0,-400 to 1000,-400 on M2 Board Dimensions
0,0 to 0,1575 on M2 Board Dimensions
0,0 to 4075,0 on M2 Board Dimensions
